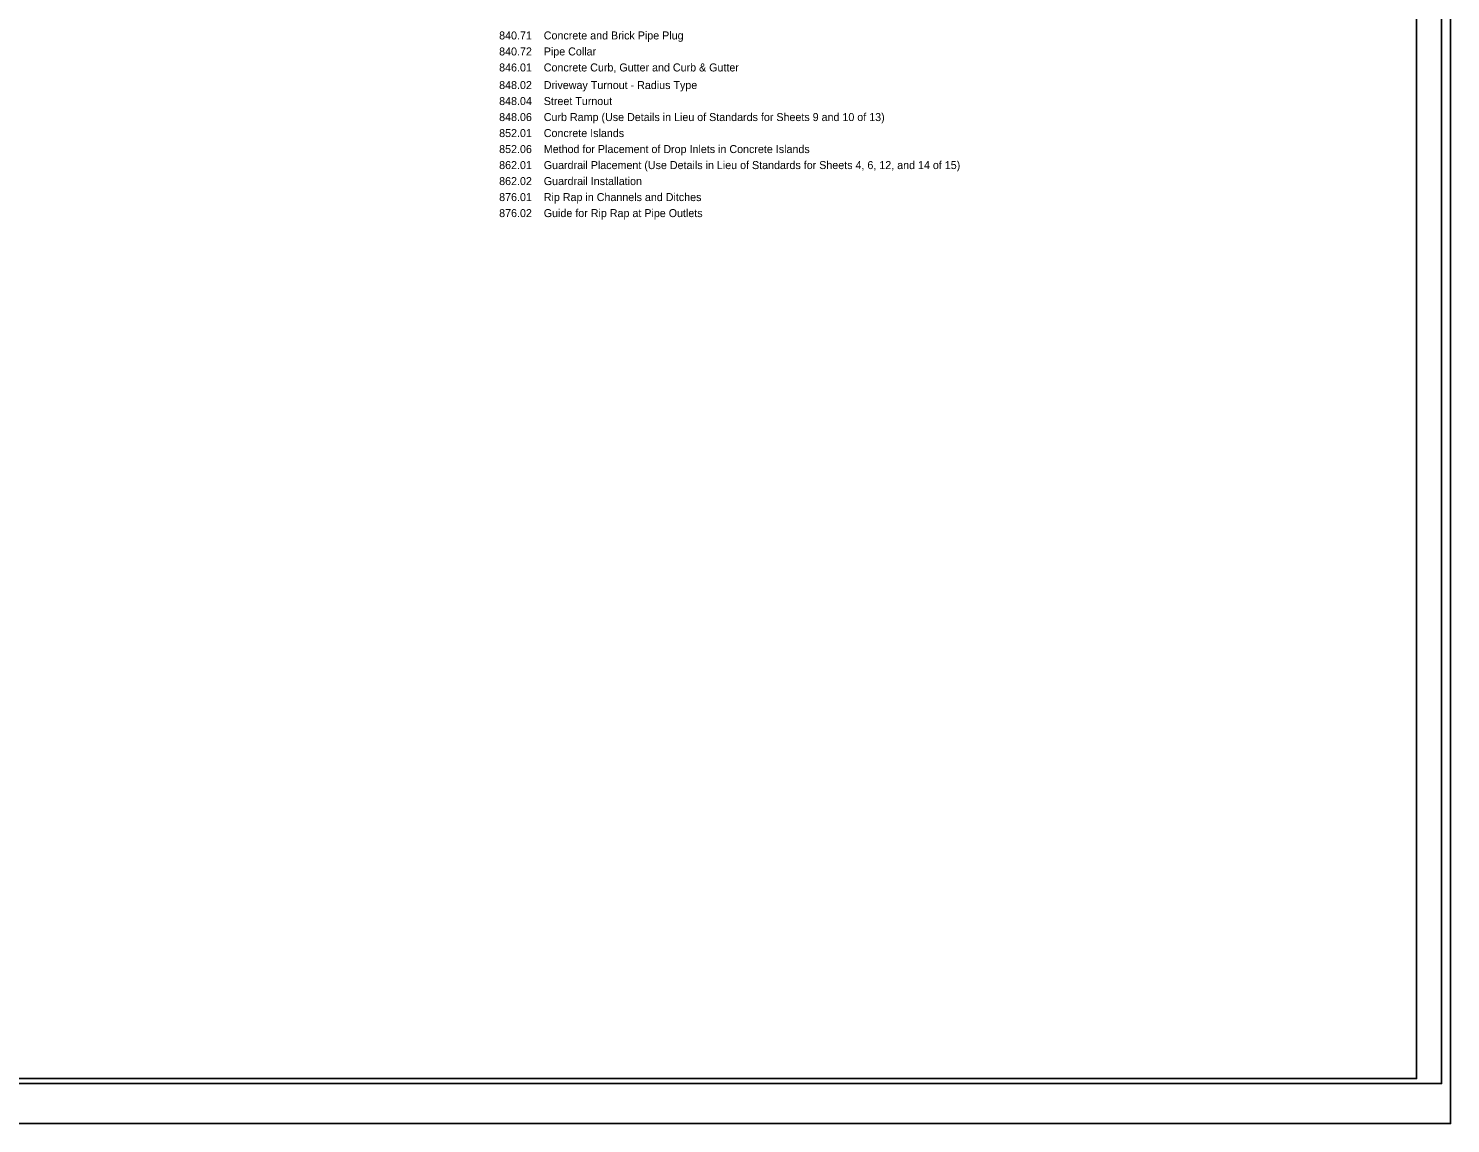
# Model space of a CAD drawing. Extents: x 1537922 to 1539606, y 409903 to 410998.
# Drawn here: x 1538895 to 1539606, y 409903 to 410451 of the extents above; entities that cross this region are included whole.
import ezdxf

# ---------------------------------------------------------------- set-up
doc = ezdxf.new("R2010")
doc.units = 0
for name, color, linetype in [('Old_Level_1', 7, 'Continuous'), ('Sheet Cutting Line CELL', 7, 'Continuous'), ('Sheet Plan CELL', 7, 'Continuous'), ('Sheet Plot Border Inside CELL', 7, 'Continuous'), ('Sheet Plot Border Outside CELL', 7, 'Continuous')]:
    doc.layers.add(name, color=color, linetype=linetype)

msp = doc.modelspace()

# ---------------------------------------------------------------- linework, layer by layer
at = {"layer": 'Sheet Cutting Line CELL'}
msp.add_line((1537922.37, 409903.35), (1539605.87, 409903.35), dxfattribs=at)
at = {"layer": 'Sheet Plan CELL'}
msp.add_lwpolyline([(1539588.87, 410975.85), (1538088.87, 410975.85), (1538088.87, 409925.85), (1539588.87, 409925.85)], close=True, dxfattribs=at)
at = {"layer": 'Sheet Plot Border Inside CELL'}
msp.add_lwpolyline([(1537935.37, 409923.35), (1539601.37, 409923.35), (1539601.37, 410978.35), (1537935.37, 410978.35)], close=True, dxfattribs=at)
at = {"layer": 'Sheet Plot Border Outside CELL'}
msp.add_lwpolyline([(1537922.37, 409903.35), (1539605.87, 409903.35), (1539605.87, 410998.35), (1537922.37, 410998.35)], close=True, dxfattribs=at)

# ---------------------------------------------------------------- texts
at = {"layer": 'Old_Level_1'}
for s, p in [('840.71    Concrete and Brick Pipe Plug', (1539130.41, 410445.24)), ('840.72    Pipe Collar', (1539130.41, 410437.24)), ('846.01    Concrete Curb, Gutter and Curb & Gutter', (1539130.41, 410429.24)), ('848.02    Driveway Turnout - Radius Type', (1539130.41, 410420.44)), ('848.04    Street Turnout', (1539130.41, 410412.44)), ('848.06    Curb Ramp (Use Details in Lieu of Standards for Sheets 9 and 10 of 13)', (1539130.41, 410404.44)), ('852.01    Concrete Islands', (1539130.41, 410396.44)), ('852.06    Method for Placement of Drop Inlets in Concrete Islands', (1539130.41, 410388.44)), ('862.01    Guardrail Placement (Use Details in Lieu of Standards for Sheets 4, 6, 12, and 14 of 15)', (1539130.41, 410380.44)), ('862.02    Guardrail Installation', (1539130.41, 410372.44)), ('876.01    Rip Rap in Channels and Ditches', (1539130.41, 410364.44)), ('876.02    Guide for Rip Rap at Pipe Outlets', (1539130.41, 410356.44))]:
    msp.add_text(s, height=4, dxfattribs=at).set_placement(p)

doc.saveas('drawing.dxf')
